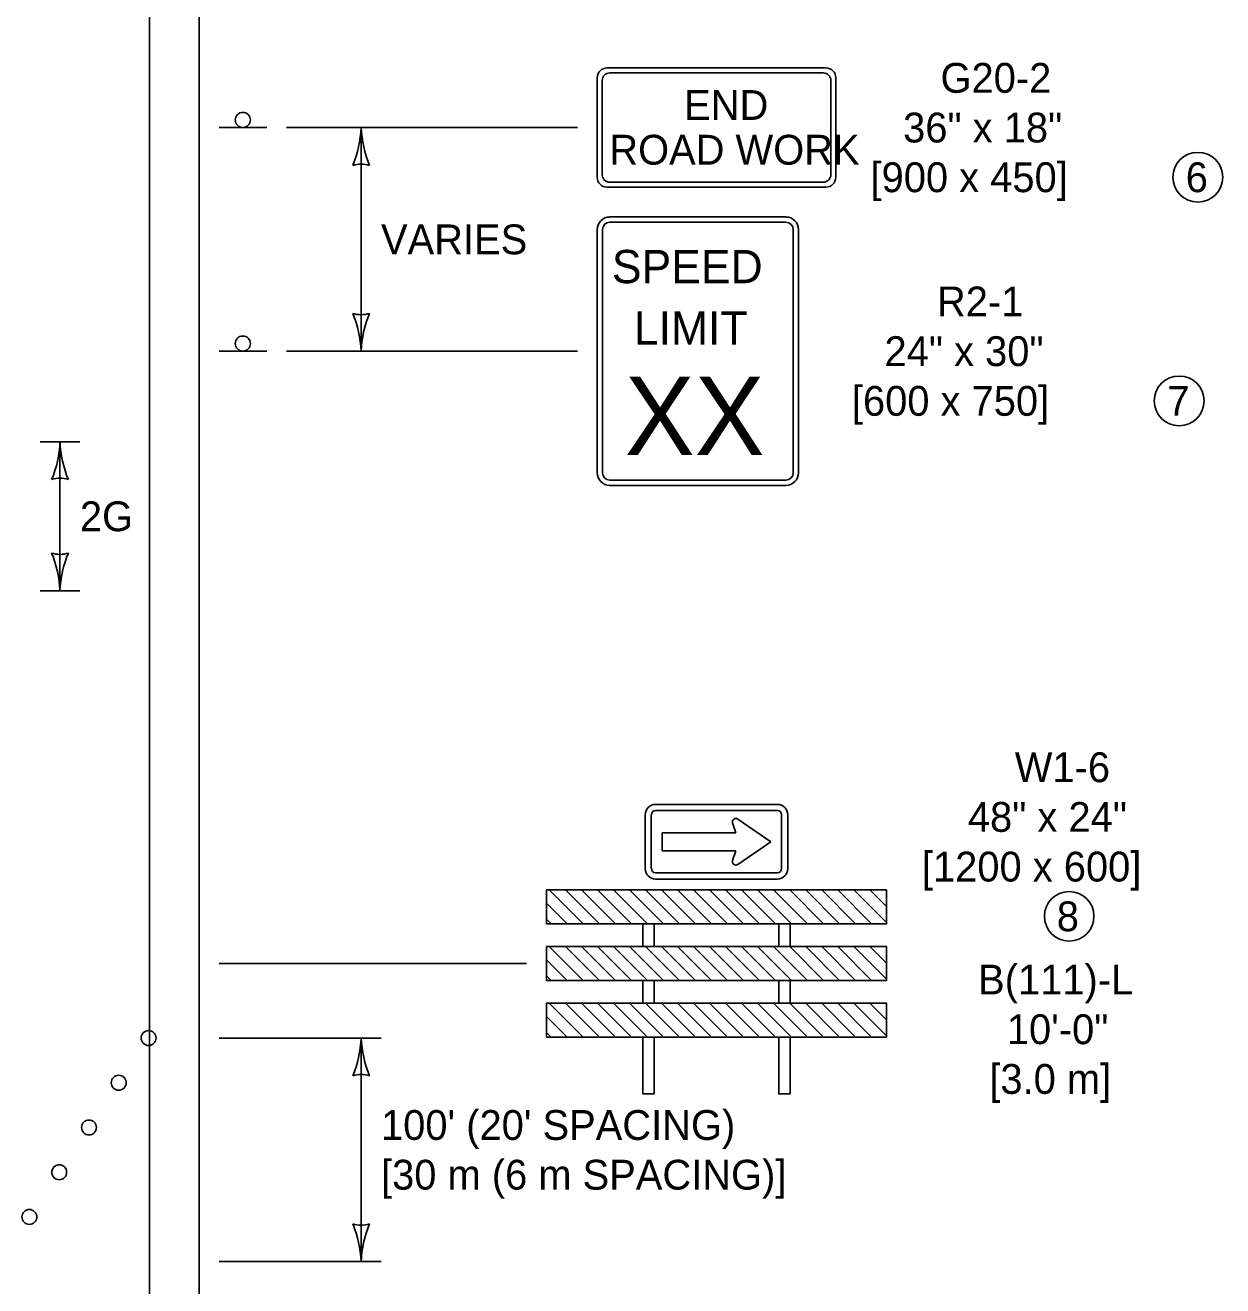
# Model space of a CAD drawing. Extents: x 49991.4 to 50021, y 49987.6 to 50011.4.
# Drawn here: x 50002.651 to 50005.061, y 50006.073 to 50008.61 of the extents above; entities that cross this region are included whole.
import ezdxf

# ---------------------------------------------------------------- set-up
doc = ezdxf.new("R2010")
doc.units = 0
for name, color, linetype in [('Level 1', 7, 'Continuous'), ('Level 2', 7, 'Continuous'), ('Level 3', 7, 'Continuous')]:
    doc.layers.add(name, color=color, linetype=linetype)

msp = doc.modelspace()

# ---------------------------------------------------------------- linework, layer by layer
at = {"layer": 'Level 1'}
for p, q in [((50002.901, 50005.8214), (50002.901, 50010.7538)), ((50003.001, 50000.5714), (50003.001, 50010.7538)), ((50004.2622, 50008.5237), (50003.8222, 50008.5237)), ((50003.8022, 50008.3037), (50003.8022, 50008.5037)), ((50003.8122, 50008.3087), (50003.8122, 50008.4987)), ((50004.2572, 50008.5137), (50003.8272, 50008.5137)), ((50004.2722, 50008.4987), (50004.2722, 50008.3087)), ((50004.2822, 50008.5037), (50004.2822, 50008.3037)), ((50003.137, 50008.4037), (50003.041, 50008.4037)), ((50004.2572, 50008.2937), (50003.8272, 50008.2937)), ((50004.2621, 50008.2837), (50003.8221, 50008.2837)), ((50003.8275, 50008.2238), (50004.1819, 50008.2238)), ((50004.0047, 50008.2238), (50004.0047, 50008.2238)), ((50003.8021, 50007.709), (50003.8021, 50008.1984)), ((50003.8127, 50007.709), (50003.8127, 50008.1984)), ((50003.8275, 50008.2132), (50004.1819, 50008.2132)), ((50004.1967, 50008.1984), (50004.1967, 50007.709)), ((50004.2072, 50008.1984), (50004.2072, 50007.709)), ((50003.137, 50007.9537), (50003.041, 50007.9537)), ((50004.1819, 50007.6942), (50003.8275, 50007.6942)), ((50004.1819, 50007.6837), (50003.8275, 50007.6837)), ((50004.1647, 50007.0415), (50003.9196, 50007.0415)), ((50004.1647, 50007.0291), (50003.9196, 50007.0291)), ((50003.8986, 50007.0206), (50003.8986, 50006.9123)), ((50003.911, 50007.0206), (50003.911, 50006.9123)), ((50004.0746, 50007.0042), (50004.081, 50006.9847)), ((50004.1516, 50006.9664), (50004.0852, 50007.0121)), ((50004.1732, 50006.9123), (50004.1732, 50007.0206)), ((50004.1856, 50006.9123), (50004.1856, 50007.0206)), ((50004.0708, 50006.9847), (50003.9326, 50006.9847)), ((50003.9326, 50006.9847), (50003.9326, 50006.9482)), ((50004.081, 50006.9847), (50004.0708, 50006.9847)), ((50004.0852, 50006.9207), (50004.1516, 50006.9664)), ((50003.9326, 50006.9482), (50004.081, 50006.9482)), ((50004.081, 50006.9482), (50004.0746, 50006.9286)), ((50003.9196, 50006.9037), (50004.1647, 50006.9037)), ((50003.9196, 50006.8913), (50004.1647, 50006.8913)), ((50003.7741, 50006.8011), (50003.7057, 50006.8695)), ((50003.7057, 50006.8695), (50003.7741, 50006.8011)), ((50003.8064, 50006.8011), (50003.738, 50006.8695)), ((50003.8064, 50006.8011), (50003.738, 50006.8695)), ((50003.8387, 50006.8011), (50003.7703, 50006.8695)), ((50003.7703, 50006.8695), (50003.8387, 50006.8011)), ((50003.8709, 50006.8011), (50003.8025, 50006.8695)), ((50003.8709, 50006.8011), (50003.8025, 50006.8695)), ((50003.9031, 50006.8011), (50003.8347, 50006.8695)), ((50003.8347, 50006.8695), (50003.9031, 50006.8011)), ((50003.9354, 50006.8011), (50003.867, 50006.8695)), ((50003.9676, 50006.8011), (50003.8992, 50006.8695)), ((50003.8992, 50006.8695), (50003.9391, 50006.8695)), ((50003.9196, 50006.8695), (50004.1647, 50006.8695)), ((50003.9998, 50006.8011), (50003.9314, 50006.8695)), ((50004.032, 50006.8011), (50003.9636, 50006.8695)), ((50004.0642, 50006.8011), (50003.9958, 50006.8695)), ((50004.0964, 50006.8011), (50004.028, 50006.8695)), ((50004.1286, 50006.8011), (50004.0602, 50006.8695)), ((50004.1608, 50006.8011), (50004.0924, 50006.8695)), ((50004.1933, 50006.8011), (50004.1249, 50006.8695)), ((50004.1789, 50006.8695), (50004.1476, 50006.8695)), ((50004.2255, 50006.8011), (50004.1571, 50006.8695)), ((50004.2578, 50006.8011), (50004.1894, 50006.8695)), ((50004.2578, 50006.8011), (50004.1894, 50006.8695)), ((50004.29, 50006.8011), (50004.2216, 50006.8695)), ((50004.2216, 50006.8695), (50004.29, 50006.8011)), ((50004.3222, 50006.8011), (50004.2538, 50006.8695)), ((50004.3222, 50006.8011), (50004.2538, 50006.8695)), ((50004.3544, 50006.8011), (50004.286, 50006.8695)), ((50004.286, 50006.8695), (50004.3544, 50006.8011)), ((50004.3841, 50006.8037), (50004.3183, 50006.8695)), ((50004.3841, 50006.8037), (50004.3183, 50006.8695)), ((50004.3841, 50006.8359), (50004.3506, 50006.8695)), ((50004.3506, 50006.8695), (50004.3841, 50006.8359)), ((50003.7419, 50006.8011), (50003.7001, 50006.8429)), ((50003.7419, 50006.8011), (50003.7001, 50006.8429)), ((50003.7097, 50006.8011), (50003.7001, 50006.8106)), ((50003.7001, 50006.8106), (50003.7097, 50006.8011)), ((50003.9167, 50006.7556), (50003.9167, 50006.8011)), ((50004.1675, 50006.7556), (50004.1675, 50006.8011)), ((50003.7741, 50006.6872), (50003.7057, 50006.7556)), ((50003.7057, 50006.7556), (50003.7741, 50006.6872)), ((50003.8064, 50006.6872), (50003.738, 50006.7556)), ((50003.8064, 50006.6872), (50003.738, 50006.7556)), ((50003.8387, 50006.6872), (50003.7703, 50006.7556)), ((50003.7703, 50006.7556), (50003.8387, 50006.6872)), ((50003.8709, 50006.6872), (50003.8025, 50006.7556)), ((50003.8709, 50006.6872), (50003.8025, 50006.7556)), ((50003.9031, 50006.6872), (50003.8347, 50006.7556)), ((50003.8347, 50006.7556), (50003.9031, 50006.6872)), ((50003.9053, 50006.7172), (50003.867, 50006.7556)), ((50003.9053, 50006.7494), (50003.8992, 50006.7556)), ((50003.9676, 50006.6872), (50003.9053, 50006.7494)), ((50003.9999, 50006.6872), (50003.9315, 50006.7556)), ((50004.0321, 50006.6872), (50003.9637, 50006.7556)), ((50004.0643, 50006.6872), (50003.9959, 50006.7556)), ((50004.0966, 50006.6872), (50004.0282, 50006.7556)), ((50004.1288, 50006.6872), (50004.0604, 50006.7556)), ((50004.161, 50006.6872), (50004.0926, 50006.7556)), ((50004.1933, 50006.6872), (50004.1249, 50006.7556)), ((50004.2255, 50006.6872), (50004.1571, 50006.7556)), ((50004.2578, 50006.6872), (50004.1894, 50006.7556)), ((50004.2578, 50006.6872), (50004.1894, 50006.7556)), ((50004.29, 50006.6872), (50004.2216, 50006.7556)), ((50004.2216, 50006.7556), (50004.29, 50006.6872)), ((50004.3222, 50006.6872), (50004.2538, 50006.7556)), ((50004.3222, 50006.6872), (50004.2538, 50006.7556)), ((50004.3544, 50006.6872), (50004.286, 50006.7556)), ((50004.286, 50006.7556), (50004.3544, 50006.6872)), ((50004.3841, 50006.6897), (50004.3183, 50006.7556)), ((50004.3841, 50006.6897), (50004.3183, 50006.7556)), ((50004.3841, 50006.7219), (50004.3506, 50006.7556)), ((50004.3506, 50006.7556), (50004.3841, 50006.7219)), ((50003.7419, 50006.6872), (50003.7001, 50006.7289)), ((50003.7419, 50006.6872), (50003.7001, 50006.7289)), ((50003.7097, 50006.6872), (50003.7001, 50006.6967)), ((50003.7001, 50006.6967), (50003.7097, 50006.6872)), ((50003.9354, 50006.6872), (50003.9053, 50006.7172)), ((50003.7741, 50006.5732), (50003.7057, 50006.6416)), ((50003.7057, 50006.6416), (50003.7741, 50006.5732)), ((50003.8064, 50006.5732), (50003.738, 50006.6416)), ((50003.8064, 50006.5732), (50003.738, 50006.6416)), ((50003.8387, 50006.5732), (50003.7703, 50006.6416)), ((50003.7703, 50006.6416), (50003.8387, 50006.5732)), ((50003.8709, 50006.5732), (50003.8025, 50006.6416)), ((50003.8709, 50006.5732), (50003.8025, 50006.6416)), ((50003.9031, 50006.5732), (50003.8347, 50006.6416)), ((50003.8347, 50006.6416), (50003.9031, 50006.5732)), ((50003.9354, 50006.5732), (50003.867, 50006.6416)), ((50003.9354, 50006.5732), (50003.867, 50006.6416)), ((50003.9676, 50006.5732), (50003.8992, 50006.6416)), ((50003.8992, 50006.6416), (50003.9676, 50006.5732)), ((50003.9999, 50006.5732), (50003.9315, 50006.6416)), ((50003.9999, 50006.5732), (50003.9315, 50006.6416)), ((50004.0321, 50006.5732), (50003.9637, 50006.6416)), ((50003.9637, 50006.6416), (50004.0321, 50006.5732)), ((50004.0643, 50006.5732), (50003.9959, 50006.6416)), ((50004.0643, 50006.5732), (50003.9959, 50006.6416)), ((50004.0966, 50006.5732), (50004.0282, 50006.6416)), ((50004.0282, 50006.6416), (50004.0966, 50006.5732)), ((50004.1288, 50006.5732), (50004.0604, 50006.6416)), ((50004.1288, 50006.5732), (50004.0604, 50006.6416)), ((50004.161, 50006.5732), (50004.0926, 50006.6416)), ((50004.0926, 50006.6416), (50004.161, 50006.5732)), ((50004.1933, 50006.5732), (50004.1249, 50006.6416)), ((50004.1933, 50006.5732), (50004.1249, 50006.6416)), ((50004.2255, 50006.5732), (50004.1571, 50006.6416)), ((50004.1571, 50006.6416), (50004.2255, 50006.5732)), ((50004.2578, 50006.5732), (50004.1894, 50006.6416)), ((50004.2578, 50006.5732), (50004.1894, 50006.6416)), ((50004.29, 50006.5732), (50004.2216, 50006.6416)), ((50004.2216, 50006.6416), (50004.29, 50006.5732)), ((50004.3222, 50006.5732), (50004.2538, 50006.6416)), ((50004.3222, 50006.5732), (50004.2538, 50006.6416)), ((50004.3544, 50006.5732), (50004.286, 50006.6416)), ((50004.286, 50006.6416), (50004.3544, 50006.5732)), ((50004.3841, 50006.5757), (50004.3183, 50006.6416)), ((50004.3841, 50006.5757), (50004.3183, 50006.6416)), ((50004.3841, 50006.608), (50004.3506, 50006.6416)), ((50004.3506, 50006.6416), (50004.3841, 50006.608)), ((50003.7419, 50006.5732), (50003.7001, 50006.615)), ((50003.7419, 50006.5732), (50003.7001, 50006.615)), ((50003.7097, 50006.5732), (50003.7001, 50006.5827)), ((50003.7001, 50006.5827), (50003.7097, 50006.5732))]:
    msp.add_line(p, q, dxfattribs=at)
for points in [[(50003.9053, 50006.8695), (50003.7001, 50006.8695), (50003.7001, 50006.8011), (50003.9053, 50006.8011)], [(50003.7001, 50006.8429), (50003.7001, 50006.8695), (50003.7057, 50006.8695)], [(50003.738, 50006.8695), (50003.7703, 50006.8695)], [(50003.8025, 50006.8695), (50003.8347, 50006.8695)], [(50003.9676, 50006.8011), (50003.9354, 50006.8011), (50003.867, 50006.8695), (50003.8992, 50006.8695), (50003.9676, 50006.8011)], [(50003.9053, 50006.8011), (50004.3841, 50006.8011), (50004.3841, 50006.8695), (50004.1789, 50006.8695)], [(50003.9314, 50006.8695), (50003.9391, 50006.8695), (50003.9636, 50006.8695), (50004.032, 50006.8011), (50003.9998, 50006.8011), (50003.9314, 50006.8695)], [(50003.9958, 50006.8695), (50004.028, 50006.8695), (50004.0964, 50006.8011), (50004.0642, 50006.8011), (50003.9958, 50006.8695)], [(50004.0602, 50006.8695), (50004.0924, 50006.8695), (50004.1608, 50006.8011), (50004.1286, 50006.8011), (50004.0602, 50006.8695)], [(50004.1249, 50006.8695), (50004.1476, 50006.8695), (50004.1571, 50006.8695), (50004.2255, 50006.8011), (50004.1933, 50006.8011), (50004.1249, 50006.8695)], [(50004.1894, 50006.8695), (50004.2216, 50006.8695)], [(50004.2538, 50006.8695), (50004.286, 50006.8695)], [(50004.3183, 50006.8695), (50004.3506, 50006.8695)], [(50004.3841, 50006.8359), (50004.3841, 50006.8037)], [(50003.7097, 50006.8011), (50003.7001, 50006.8011), (50003.7001, 50006.8106)], [(50003.7741, 50006.8011), (50003.7419, 50006.8011)], [(50003.8387, 50006.8011), (50003.8064, 50006.8011)], [(50003.9031, 50006.8011), (50003.8709, 50006.8011)], [(50003.8939, 50006.8011), (50003.8939, 50006.7556)], [(50004.1903, 50006.7555), (50004.1903, 50006.8011)], [(50004.29, 50006.8011), (50004.2578, 50006.8011)], [(50004.3544, 50006.8011), (50004.3222, 50006.8011)], [(50003.9053, 50006.7556), (50003.7001, 50006.7556), (50003.7001, 50006.6872), (50004.3841, 50006.6872), (50004.3841, 50006.7556), (50003.9053, 50006.7556)], [(50003.7001, 50006.7289), (50003.7001, 50006.7556), (50003.7057, 50006.7556)], [(50003.738, 50006.7556), (50003.7703, 50006.7556)], [(50003.8025, 50006.7556), (50003.8347, 50006.7556)], [(50003.9676, 50006.6872), (50003.9354, 50006.6872), (50003.9053, 50006.7172), (50003.867, 50006.7556), (50003.8939, 50006.7556), (50003.8992, 50006.7556), (50003.9053, 50006.7494), (50003.9676, 50006.6872)], [(50003.9315, 50006.7556), (50003.9637, 50006.7556), (50004.0321, 50006.6872), (50003.9999, 50006.6872), (50003.9315, 50006.7556)], [(50003.9959, 50006.7556), (50004.0282, 50006.7556), (50004.0966, 50006.6872), (50004.0643, 50006.6872), (50003.9959, 50006.7556)], [(50004.0604, 50006.7556), (50004.0926, 50006.7556), (50004.161, 50006.6872), (50004.1288, 50006.6872), (50004.0604, 50006.7556)], [(50004.1249, 50006.7556), (50004.1571, 50006.7556), (50004.2255, 50006.6872), (50004.1933, 50006.6872), (50004.1249, 50006.7556)], [(50004.1894, 50006.7556), (50004.2216, 50006.7556)], [(50004.2538, 50006.7556), (50004.286, 50006.7556)], [(50004.3183, 50006.7556), (50004.3506, 50006.7556)], [(50004.3841, 50006.7219), (50004.3841, 50006.6897)], [(50003.7097, 50006.6872), (50003.7001, 50006.6872), (50003.7001, 50006.6967)], [(50003.7741, 50006.6872), (50003.7419, 50006.6872)], [(50003.8387, 50006.6872), (50003.8064, 50006.6872)], [(50003.9031, 50006.6872), (50003.8709, 50006.6872)], [(50003.8939, 50006.6872), (50003.8939, 50006.6416)], [(50003.9167, 50006.6416), (50003.9167, 50006.6872)], [(50004.1675, 50006.6872), (50004.1675, 50006.6416)], [(50004.1903, 50006.6416), (50004.1903, 50006.6872)], [(50004.29, 50006.6872), (50004.2578, 50006.6872)], [(50004.3544, 50006.6872), (50004.3222, 50006.6872)], [(50003.7001, 50006.615), (50003.7001, 50006.6416), (50003.7057, 50006.6416)], [(50003.867, 50006.6416), (50003.7001, 50006.6416), (50003.7001, 50006.5732), (50004.3841, 50006.5732), (50004.3841, 50006.6416), (50004.2216, 50006.6416)], [(50003.738, 50006.6416), (50003.7703, 50006.6416)], [(50003.8025, 50006.6416), (50003.8347, 50006.6416)], [(50003.867, 50006.6416), (50003.8992, 50006.6416)], [(50004.1894, 50006.6416), (50003.8992, 50006.6416)], [(50003.9315, 50006.6416), (50003.9637, 50006.6416)], [(50003.9959, 50006.6416), (50004.0282, 50006.6416)], [(50004.0604, 50006.6416), (50004.0926, 50006.6416)], [(50004.1249, 50006.6416), (50004.1571, 50006.6416)], [(50004.1894, 50006.6416), (50004.2216, 50006.6416)], [(50004.2538, 50006.6416), (50004.286, 50006.6416)], [(50004.3183, 50006.6416), (50004.3506, 50006.6416)], [(50004.3841, 50006.608), (50004.3841, 50006.5757)], [(50003.7097, 50006.5732), (50003.7001, 50006.5732), (50003.7001, 50006.5827)], [(50003.7741, 50006.5732), (50003.7419, 50006.5732)], [(50003.8387, 50006.5732), (50003.8064, 50006.5732)], [(50003.9031, 50006.5732), (50003.8709, 50006.5732)], [(50003.8939, 50006.5731), (50003.8939, 50006.4591), (50003.9167, 50006.4591), (50003.9167, 50006.5731)], [(50003.9676, 50006.5732), (50003.9354, 50006.5732)], [(50004.0321, 50006.5732), (50003.9999, 50006.5732)], [(50004.0966, 50006.5732), (50004.0643, 50006.5732)], [(50004.161, 50006.5732), (50004.1288, 50006.5732)], [(50004.1675, 50006.5731), (50004.1675, 50006.4591), (50004.1903, 50006.4591), (50004.1903, 50006.5731)], [(50004.2255, 50006.5732), (50004.1933, 50006.5732)], [(50004.29, 50006.5732), (50004.2578, 50006.5732)], [(50004.3544, 50006.5732), (50004.3222, 50006.5732)]]:
    msp.add_lwpolyline(points, dxfattribs=at)
for centre, radius in [((50003.089, 50008.419), 0.0152), ((50003.089, 50007.969), 0.0152), ((50002.8993, 50006.5714), 0.015), ((50002.8393, 50006.4814), 0.015), ((50002.7794, 50006.3914), 0.015), ((50002.7194, 50006.3014), 0.015), ((50002.6594, 50006.2114), 0.015)]:
    msp.add_circle(centre, radius, dxfattribs=at)
for centre, radius, start, end in [((50003.8222, 50008.5037), 0.02, 90, 180), ((50004.2622, 50008.5037), 0.02, 360, 90), ((50003.8272, 50008.4987), 0.015, 90, 180), ((50004.2572, 50008.4987), 0.015, 360, 90), ((50003.8221, 50008.3037), 0.02, 180, 270), ((50003.8272, 50008.3087), 0.015, 180, 270), ((50004.2572, 50008.3087), 0.015, 270, 360), ((50004.2621, 50008.3037), 0.02, 270, 360), ((50003.8275, 50008.1984), 0.0253, 90, 180), ((50004.1819, 50008.1984), 0.0253, 0, 90), ((50003.8275, 50008.1984), 0.0148, 90, 180), ((50004.1819, 50008.1984), 0.0148, 0, 90), ((50003.8275, 50007.709), 0.0253, 180, 270), ((50003.8275, 50007.709), 0.0148, 180, 270), ((50004.1819, 50007.709), 0.0148, 270, 360), ((50004.1819, 50007.709), 0.0253, 270, 360), ((50003.9196, 50007.0206), 0.0209, 90, 180), ((50003.9196, 50007.0206), 0.00855, 90, 180), ((50004.1647, 50007.0206), 0.0209, 0, 90), ((50004.1647, 50007.0206), 0.00855, 0, 90), ((50004.0812, 50007.0064), 0.00695, 55.4806, 197.9582), ((50004.0812, 50006.9264), 0.00695, 162.0418, 304.5194), ((50003.9196, 50006.9123), 0.0209, 180, 270), ((50003.9196, 50006.9123), 0.00855, 180, 270), ((50004.1647, 50006.9123), 0.00855, 270, 360), ((50004.1647, 50006.9123), 0.0209, 270, 360)]:
    msp.add_arc(centre, radius, start, end, dxfattribs=at)
at = {"layer": 'Level 2'}
for centre, radius in [((50005.0109, 50008.3037), 0.0501), ((50004.9733, 50007.8536), 0.0501), ((50004.7519, 50006.8164), 0.0499)]:
    msp.add_circle(centre, radius, dxfattribs=at)
at = {"layer": 'Level 3'}
for p, q in [((50003.177, 50008.4037), (50003.7622, 50008.4037)), ((50003.327, 50007.9537), (50003.327, 50008.4037)), ((50003.177, 50007.9537), (50003.7621, 50007.9537)), ((50002.761, 50007.7714), (50002.681, 50007.7714)), ((50002.721, 50007.4714), (50002.721, 50007.7714)), ((50002.761, 50007.4714), (50002.681, 50007.4714)), ((50003.041, 50006.7214), (50003.6601, 50006.7214)), ((50003.041, 50006.5714), (50003.367, 50006.5714)), ((50003.327, 50006.1214), (50003.327, 50006.5714)), ((50003.041, 50006.1214), (50003.367, 50006.1214))]:
    msp.add_line(p, q, dxfattribs=at)
for centre, radius, start, end in [((50003.1049, 50008.4129), 0.2223, 337.456, 357.6395), ((50003.5597, 50008.4152), 0.233, 182.8273, 202.0772), ((50003.327, 50008.2755), 0.0548, 72.1388, 107.8612), ((50003.327, 50008.0819), 0.0548, 252.1388, 287.8612), ((50003.0943, 50007.9422), 0.233, 2.8273, 22.0772), ((50003.5491, 50007.9446), 0.2223, 157.456, 177.6395), ((50002.4989, 50007.7805), 0.2223, 337.456, 357.6395), ((50002.9537, 50007.7829), 0.233, 182.8273, 202.0772), ((50002.721, 50007.6432), 0.0548, 72.1388, 107.8612), ((50002.721, 50007.5996), 0.0548, 252.1388, 287.8612), ((50002.4883, 50007.4599), 0.233, 2.8273, 22.0772), ((50002.9431, 50007.4622), 0.2223, 157.456, 177.6395), ((50003.1049, 50006.5805), 0.2223, 337.456, 357.6395), ((50003.5597, 50006.5829), 0.233, 182.8273, 202.0772), ((50003.327, 50006.4432), 0.0548, 72.1388, 107.8612), ((50003.327, 50006.2496), 0.0548, 252.1388, 287.8612), ((50003.0943, 50006.1099), 0.233, 2.8273, 22.0772), ((50003.5491, 50006.1122), 0.2223, 157.456, 177.6395)]:
    msp.add_arc(centre, radius, start, end, dxfattribs=at)

# ---------------------------------------------------------------- texts
at = {"layer": 'Level 1'}
for s, p in [('END', (50003.977, 50008.4191)), ('ROAD WORK', (50003.8264, 50008.3291))]:
    msp.add_text(s, height=0.06, rotation=360, dxfattribs=at).set_placement(p)
for s, height, p in [('SPEED', 0.06695, (50003.8316, 50008.0905)), ('LIMIT', 0.06695, (50003.8759, 50007.9667)), ('XX', 0.15772, (50003.8576, 50007.7448))]:
    msp.add_text(s, height=height, dxfattribs=at).set_placement(p)
at = {"layer": 'Level 2'}
for s, p in [('G20-2', (50004.4929, 50008.4737)), ('36" x 18"', (50004.4177, 50008.3737)), ('[900 x 450]', (50004.3521, 50008.2737)), ('6', (50004.9864, 50008.2737)), ('VARIES', (50003.367, 50008.1487)), ('R2-1', (50004.4858, 50008.0237)), ('24" x 30"', (50004.3802, 50007.9237)), ('[600 x 750]', (50004.3146, 50007.8237)), ('7', (50004.9495, 50007.8236)), ('2G', (50002.761, 50007.5914)), ('W1-6', (50004.6424, 50007.0864)), ('48" x 24"', (50004.548, 50006.9864)), ('[1200 x 600]', (50004.4555, 50006.8864)), ('8', (50004.7269, 50006.7864)), ('B(111)-L', (50004.5686, 50006.6591)), ('10\'-0"', (50004.6264, 50006.5591)), ('[3.0 m]', (50004.5912, 50006.4591)), ("100' (20' SPACING) ", (50003.367, 50006.3664)), ('[30 m (6 m SPACING)]', (50003.367, 50006.2664))]:
    msp.add_text(s, height=0.06, dxfattribs=at).set_placement(p)

doc.saveas('drawing.dxf')
